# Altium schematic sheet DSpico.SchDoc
size A3; CompanyName: KDS; Organization: KDS; DocumentNumber: 0; Revision: V1I1; SheetNumber: 0; SheetTotal: 4; PageSetup: Record=PageOptions¦CenterHorizontal=True¦CenterVertical=True¦PrintScale=1.07¦XCorrection=1.00¦YCorrection=1.00¦PrintKind=1¦BorderSize=5000000¦LeftOffset=0¦BottomOffset=0¦Orientation=2¦PaperLength=1000¦PaperWidth=1000¦Scale=100¦PaperSource=7¦PrintQuality=600¦MediaType=1¦DitherType=10¦PaperKind=A3¦PrintScaleMode=1
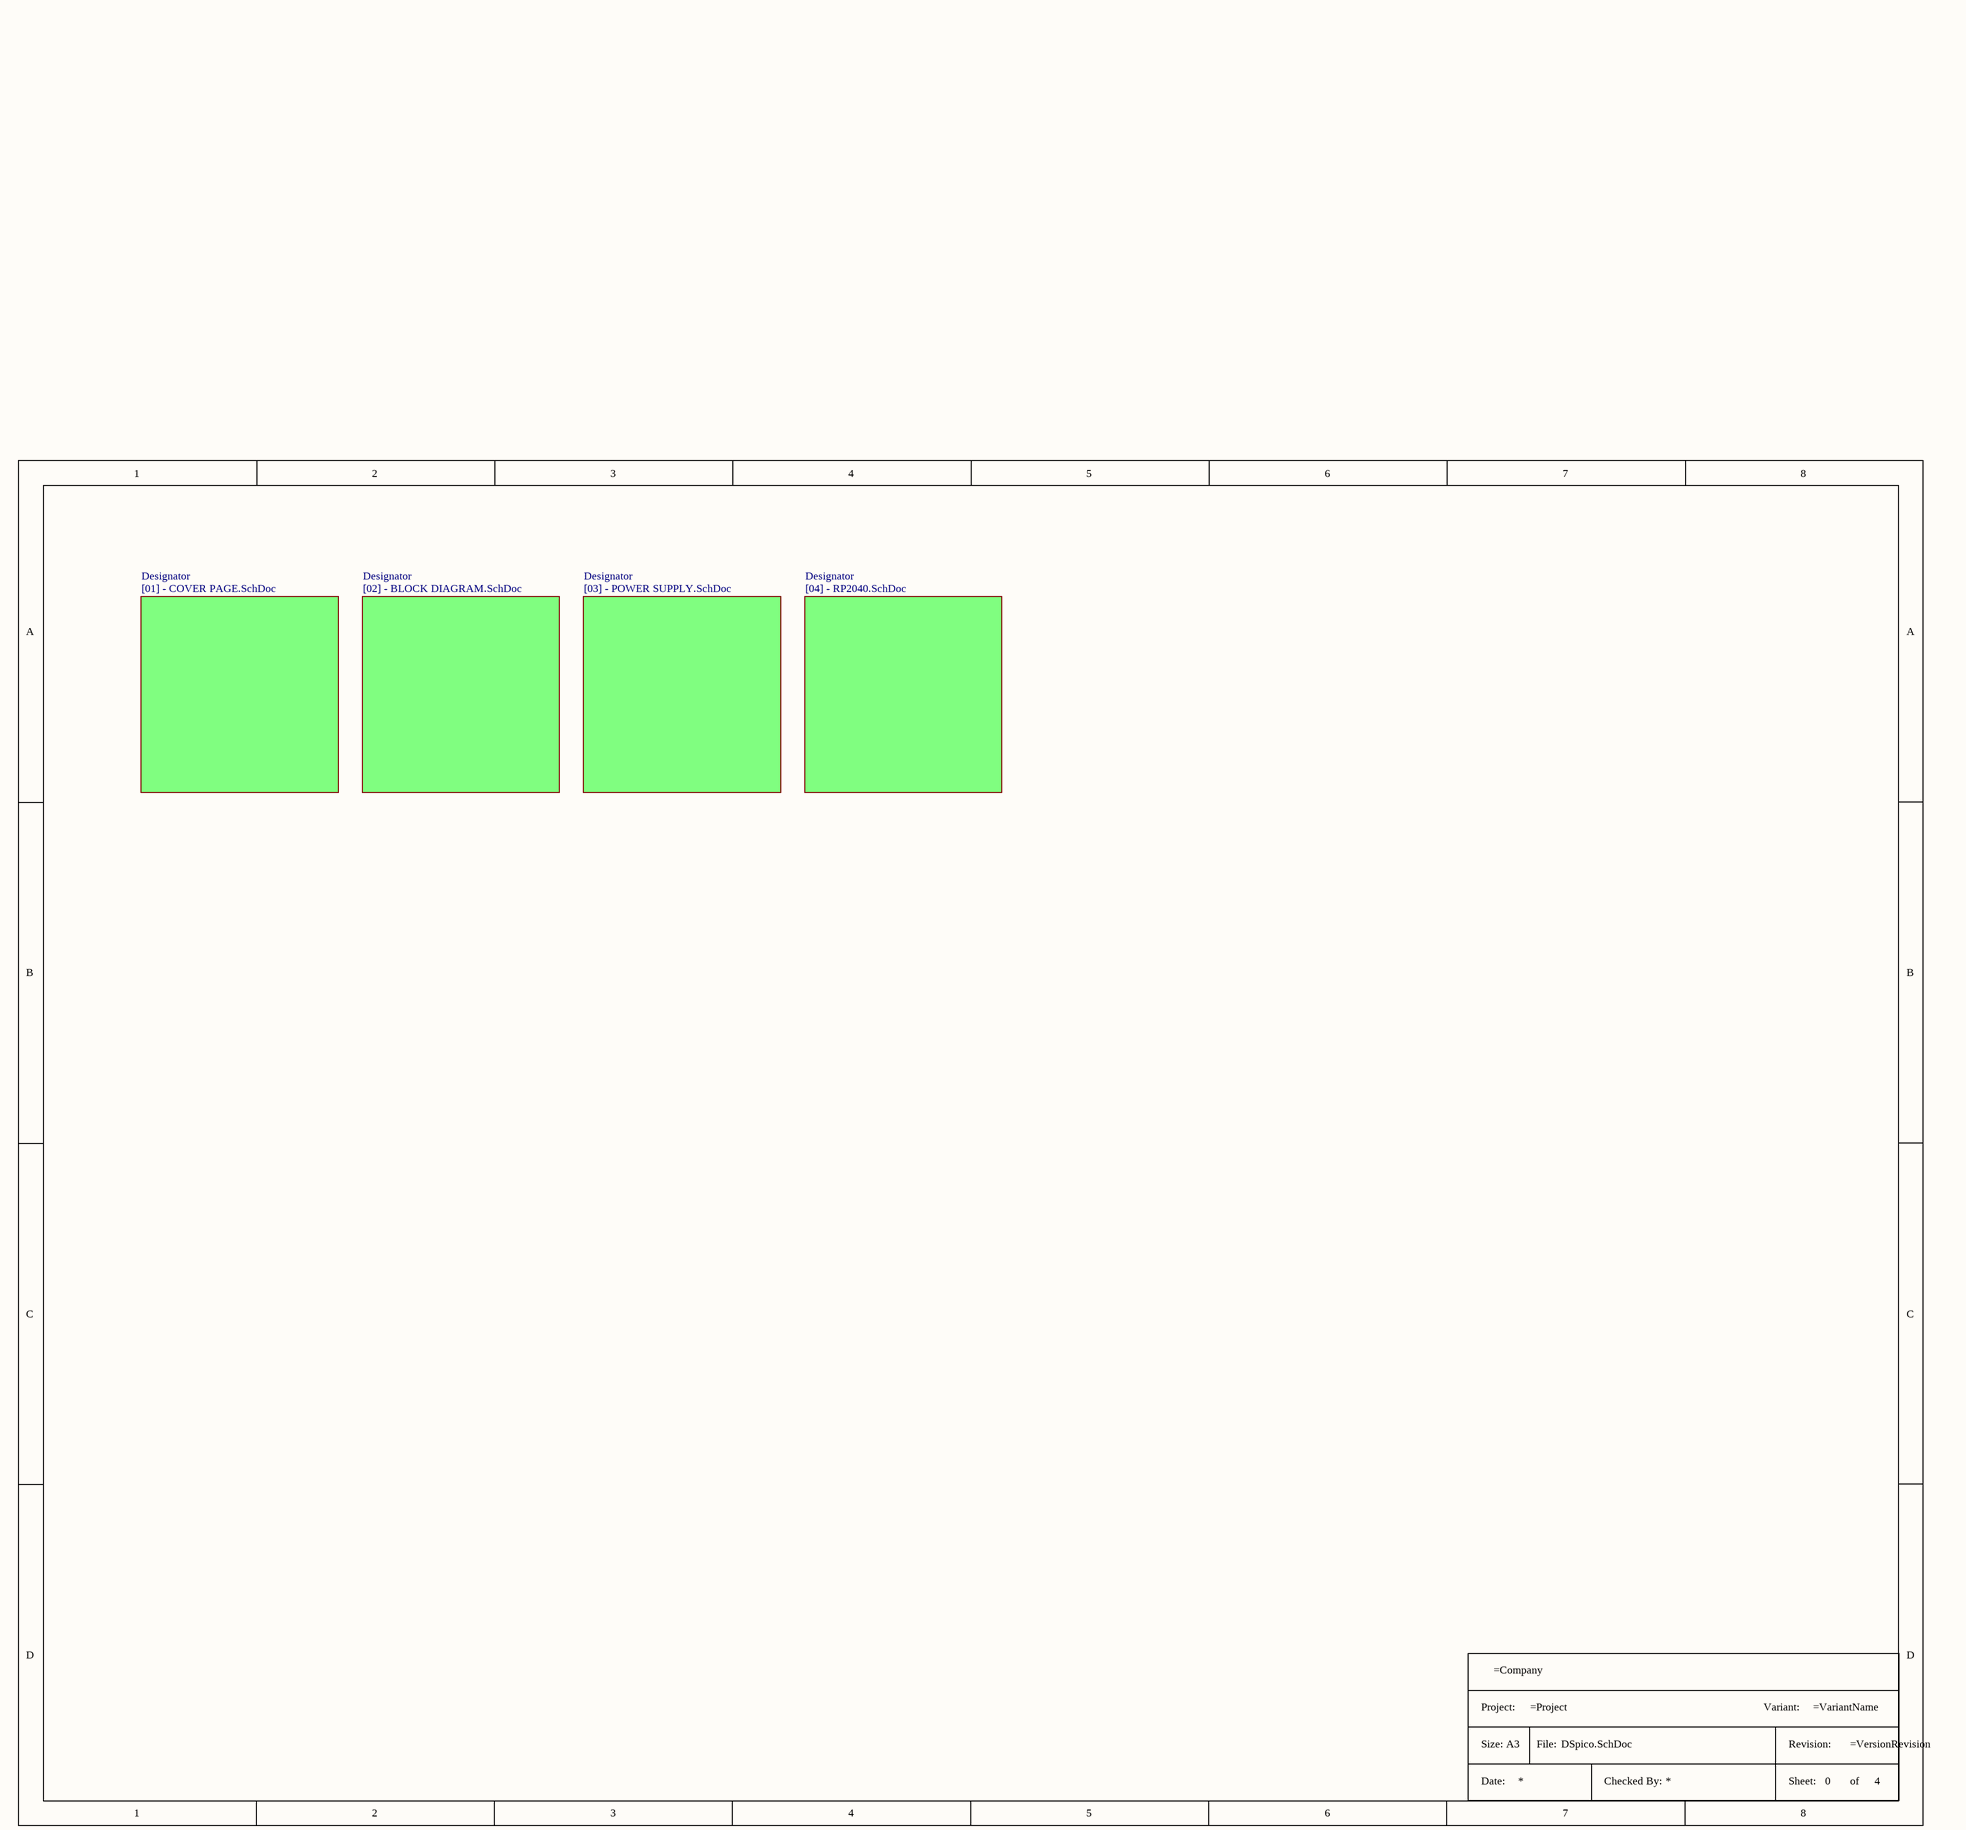
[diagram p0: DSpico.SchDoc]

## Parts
*  Title Block A3  (value not drawn)  (graphical)

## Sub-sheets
Designator = [01] - COVER PAGE.SchDoc: no entries
Designator = [03] - POWER SUPPLY.SchDoc: no entries
Designator = [02] - BLOCK DIAGRAM.SchDoc: no entries
Designator = [04] - RP2040.SchDoc: no entries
